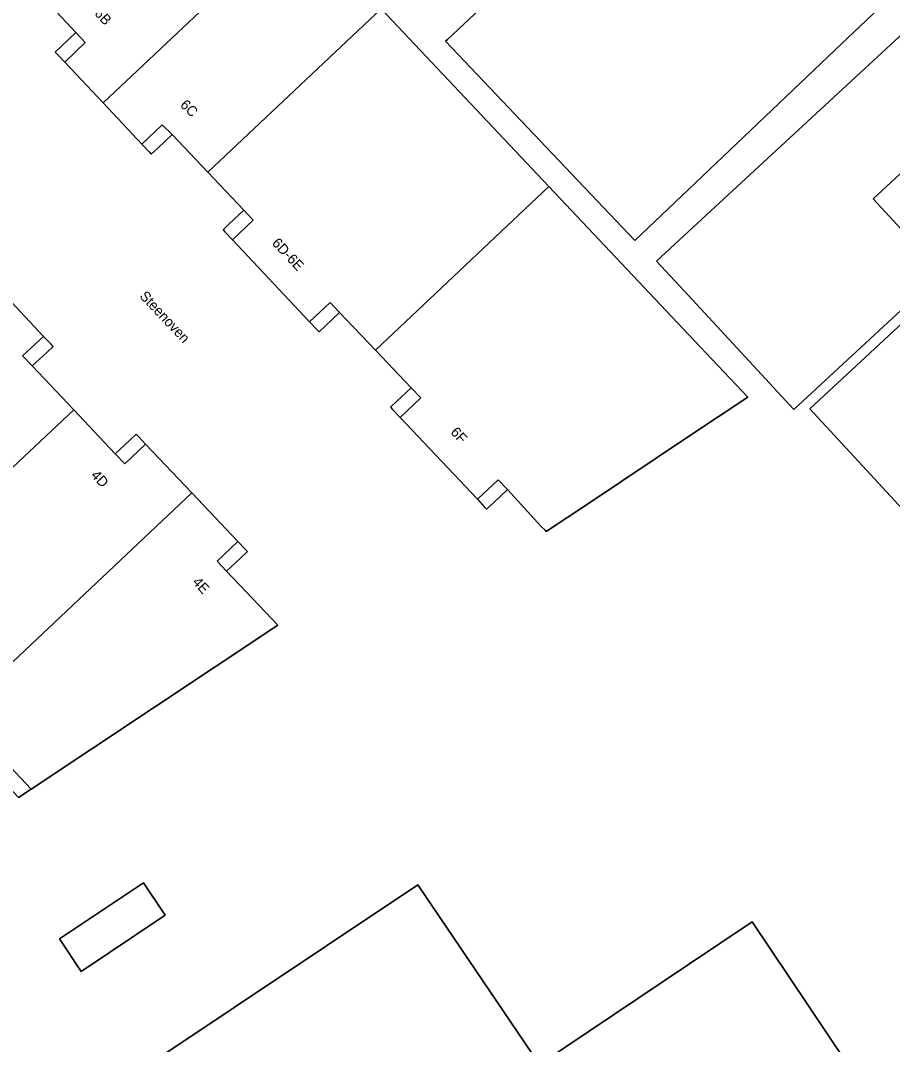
# Model space of a CAD drawing. Extents: x 156702 to 158052, y 387630 to 388992.
# Drawn here: x 157434.2 to 157520.1, y 388025.2 to 388126 of the extents above; entities that cross this region are included whole.
import ezdxf

# ---------------------------------------------------------------- set-up
doc = ezdxf.new("R2010")
doc.units = 0
for name, color, linetype in [('IMGEO_Erf', 7, 'Continuous'), ('IMGEO_Openbare_ruimte_label', 7, 'Continuous'), ('IMGEO_Pand', 7, 'Continuous'), ('IMGEO_Pand_nummerreeks', 7, 'Continuous'), ('IMGEO_Pand_overbouw', 7, 'Continuous')]:
    doc.layers.add(name, color=color, linetype=linetype)

msp = doc.modelspace()

# ---------------------------------------------------------------- linework, layer by layer
at = {"layer": 'IMGEO_Erf'}
for points in [[(157469.73, 388127.18), (157486.25, 388109.68), (157500, 388095.1), (157505.83, 388088.92), (157500, 388085.03), (157490.15, 388078.46), (157485.99, 388075.68), (157485.87, 388075.81), (157485.46, 388076.23), (157482.18, 388079.82), (157481.25, 388080.79), (157479.21, 388078.86), (157471.6, 388086.93), (157473.65, 388088.85), (157472.7, 388089.85), (157469.16, 388093.55), (157465.64, 388097.25), (157464.7, 388098.23), (157462.69, 388096.34), (157455.09, 388104.41), (157457.12, 388106.34), (157456.2, 388107.33), (157452.66, 388111.09), (157449.17, 388114.79), (157448.18, 388115.75), (157446.17, 388113.85), (157442.35, 388117.91), (157438.57, 388121.92), (157440.6, 388123.86), (157439.68, 388124.84), (157436.37, 388128.38)], [(157518.7, 388127.15), (157515.08, 388123.71), (157500, 388109.38), (157494.71, 388104.35), (157476.08, 388123.97), (157476.28, 388124.15), (157481.05, 388128.67)], [(157431.94, 388099.71), (157436.49, 388094.9), (157434.42, 388092.98), (157435.37, 388092), (157439.46, 388087.68), (157443.55, 388083.34), (157444.49, 388082.34), (157446.53, 388084.28), (157451.08, 388079.49), (157455.62, 388074.7), (157453.58, 388072.77), (157454.5, 388071.78), (157458.36, 388067.75), (157459.56, 388066.48), (157435.27, 388050.31), (157434.01, 388049.48)], [(157443.82, 388017.48), (157442.32, 388019.71), (157442.11, 388020.01), (157446.27, 388022.79), (157473.35, 388040.88), (157485.34, 388023.18), (157500, 388033.03), (157506.27, 388037.24), (157530.4, 388001.25), (157528.53, 388000), (157513.82, 387990.16), (157531.52, 387963.86), (157500, 387942.64), (157495.94, 387939.91), (157495.74, 387940.21), (157494.3, 387942.39)]]:
    msp.add_lwpolyline(points, dxfattribs=at)
for points in [[(157510.36, 388087.71), (157500, 388098.92), (157496.86, 388102.33), (157500, 388105.24), (157525.96, 388129.28), (157532.76, 388121.95), (157518.18, 388108.45), (157524.91, 388101.18)], [(157539.77, 388057.62), (157511.93, 388087.78), (157540.26, 388114.06), (157550.38, 388123.44), (157553.17, 388120.43), (157552.25, 388119.58), (157557.15, 388114.3), (157551.61, 388109.17), (157552.23, 388108.51), (157552.46, 388108.25), (157571.82, 388087.36), (157568.16, 388083.96)], [(157438.05, 388035.56), (157446.33, 388041.09), (157448.46, 388037.9), (157440.18, 388032.36)]]:
    msp.add_lwpolyline(points, close=True, dxfattribs=at)
at = {"layer": 'IMGEO_Pand'}
for points in [[(157442.35, 388117.91), (157461.47, 388135.94), (157454.32, 388143.51), (157451.12, 388146.9), (157450.97, 388147.06), (157436.06, 388128.58), (157436.37, 388128.38), (157439.68, 388124.84), (157440.6, 388123.86), (157438.57, 388121.92)], [(157480.9, 388128.82), (157481.05, 388128.67), (157476.28, 388124.15), (157476.08, 388123.97), (157494.71, 388104.35), (157500, 388109.38), (157515.08, 388123.71), (157518.7, 388127.15), (157500.11, 388146.76), (157500, 388146.65), (157490.68, 388137.81), (157490.6, 388137.9)], [(157452.66, 388111.09), (157469.73, 388127.18), (157461.47, 388135.94), (157442.35, 388117.91), (157446.17, 388113.85), (157448.18, 388115.75), (157449.17, 388114.79)], [(157510.36, 388087.71), (157524.91, 388101.18), (157518.18, 388108.45), (157532.76, 388121.95), (157525.96, 388129.28), (157500, 388105.24), (157496.86, 388102.33), (157500, 388098.92)], [(157452.66, 388111.09), (157456.2, 388107.33), (157457.12, 388106.34), (157455.09, 388104.41), (157462.69, 388096.34), (157464.7, 388098.23), (157465.64, 388097.25), (157469.16, 388093.55), (157486.25, 388109.68), (157469.73, 388127.18)], [(157552.46, 388108.25), (157552.23, 388108.51), (157551.61, 388109.17), (157557.15, 388114.3), (157552.25, 388119.58), (157553.17, 388120.43), (157550.38, 388123.44), (157540.26, 388114.06), (157511.93, 388087.78), (157539.77, 388057.62), (157568.16, 388083.96), (157571.82, 388087.36)], [(157469.16, 388093.55), (157472.7, 388089.85), (157473.65, 388088.85), (157471.6, 388086.93), (157479.21, 388078.86), (157481.25, 388080.79), (157482.18, 388079.82), (157485.46, 388076.23), (157485.87, 388075.81), (157485.99, 388075.68), (157490.15, 388078.46), (157500, 388085.03), (157505.83, 388088.92), (157500, 388095.1), (157486.25, 388109.68)], [(157439.46, 388087.68), (157435.37, 388092), (157434.42, 388092.98), (157436.49, 388094.9), (157431.94, 388099.71), (157409, 388078.12), (157407.9, 388077.09), (157417.44, 388067)], [(157439.46, 388087.68), (157417.44, 388067), (157427.05, 388056.84), (157434.01, 388049.48), (157435.27, 388050.31), (157428.15, 388057.87), (157451.08, 388079.49), (157446.53, 388084.28), (157444.49, 388082.34), (157443.55, 388083.34)], [(157435.27, 388050.31), (157459.56, 388066.48), (157458.36, 388067.75), (157454.5, 388071.78), (157453.58, 388072.77), (157455.62, 388074.7), (157451.08, 388079.49), (157428.15, 388057.87)], [(157438.05, 388035.56), (157440.18, 388032.36), (157448.46, 388037.9), (157446.33, 388041.09)]]:
    msp.add_lwpolyline(points, close=True, dxfattribs=at)
msp.add_lwpolyline([(157494.3, 387942.39), (157495.74, 387940.21), (157495.94, 387939.91), (157500, 387942.64), (157531.52, 387963.86), (157513.82, 387990.16), (157528.53, 388000), (157530.4, 388001.25), (157506.27, 388037.24), (157500, 388033.03), (157485.34, 388023.18), (157473.35, 388040.88), (157446.27, 388022.79), (157442.11, 388020.01), (157442.32, 388019.71), (157443.82, 388017.48)], dxfattribs=at)
at = {"layer": 'IMGEO_Pand_overbouw'}
for points in [[(157439.68, 388124.84), (157438.26, 388123.49), (157437.63, 388122.9), (157437.85, 388122.66), (157438.57, 388121.92), (157440.6, 388123.86)], [(157446.17, 388113.85), (157446.88, 388113.09), (157447.1, 388112.85), (157447.73, 388113.43), (157449.17, 388114.79), (157448.18, 388115.75)], [(157456.2, 388107.33), (157454.78, 388105.98), (157454.16, 388105.39), (157454.37, 388105.16), (157455.09, 388104.41), (157457.12, 388106.34)], [(157462.69, 388096.34), (157463.4, 388095.58), (157463.62, 388095.35), (157464.24, 388095.96), (157465.64, 388097.25), (157464.7, 388098.23)], [(157435.37, 388092), (157436.8, 388093.32), (157437.43, 388093.92), (157437.21, 388094.16), (157436.49, 388094.9), (157434.42, 388092.98)], [(157471.6, 388086.93), (157473.65, 388088.85), (157472.7, 388089.85), (157471.29, 388088.53), (157470.64, 388087.92), (157470.85, 388087.69)], [(157446.53, 388084.28), (157445.83, 388085.04), (157445.61, 388085.27), (157444.97, 388084.67), (157443.55, 388083.34), (157444.49, 388082.34)], [(157479.21, 388078.86), (157479.9, 388078.1), (157480.12, 388077.88), (157480.75, 388078.49), (157482.18, 388079.82), (157481.25, 388080.79)], [(157454.5, 388071.78), (157455.93, 388073.11), (157456.56, 388073.72), (157456.34, 388073.95), (157455.62, 388074.7), (157453.58, 388072.77)]]:
    msp.add_lwpolyline(points, close=True, dxfattribs=at)

# ---------------------------------------------------------------- texts
at = {"layer": 'IMGEO_Openbare_ruimte_label'}
msp.add_text('Steenoven', height=1, rotation=313.338, dxfattribs=at).set_placement((157445.88, 388098.81))
at = {"layer": 'IMGEO_Pand_nummerreeks'}
for s, rotation, p in [('6B', 313.0999, (157441.43, 388126.66)), ('6C', 315.9382, (157449.87, 388117.62)), ('6D-6E', 313.2893, (157458.91, 388104.03)), ('6F', 313.3185, (157476.5, 388085.41)), ('4D', 313.3483, (157441.09, 388081.17)), ('4E', 312.8389, (157451.08, 388070.65))]:
    msp.add_text(s, height=1, rotation=rotation, dxfattribs=at).set_placement(p)

doc.saveas('drawing.dxf')
